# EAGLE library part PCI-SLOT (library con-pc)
PCI SLOT
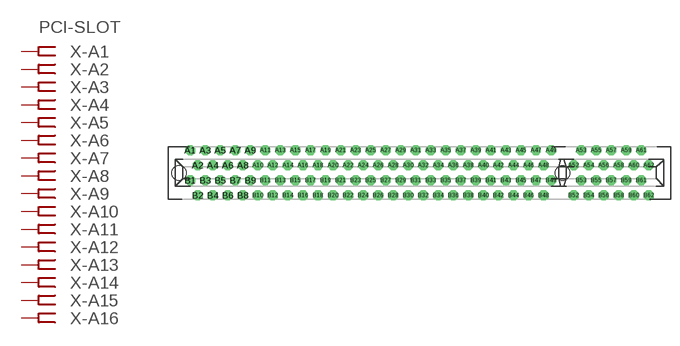
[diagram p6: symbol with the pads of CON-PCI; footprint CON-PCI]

Designator prefix X; gates -A1=FEMRVAL -A2=FEMREC -A3=FEMREC -A4=FEMREC -A5=FEMREC -A6=FEMREC -A7=FEMREC -A8=FEMREC -A9=FEMREC -A10=FEMREC -A11=FEMREC -A12=FEMREC -A13=FEMREC -A14=FEMREC -A15=FEMREC -A16=FEMREC -A17=FEMREC -A18=FEMREC -A19=FEMREC -A20=FEMREC -A21=FEMREC -A22=FEMREC -A23=FEMREC -A24=FEMREC -A25=FEMREC -A26=FEMREC -A27=FEMREC -A28=FEMREC -A29=FEMREC -A30=FEMREC -A31=FEMREC -A32=FEMREC -A33=FEMREC -A34=FEMREC -A35=FEMREC -A36=FEMREC -A37=FEMREC -A38=FEMREC -A39=FEMREC -A40=FEMREC -A41=FEMREC -A42=FEMREC -A43=FEMREC -A44=FEMREC -A45=FEMREC -A46=FEMREC -A47=FEMREC -A48=FEMREC -A49=FEMREC -A52=FEMREC -A53=FEMREC -A54=FEMREC -A55=FEMREC -A56=FEMREC -A57=FEMREC -A58=FEMREC -A59=FEMREC -A60=FEMREC -A61=FEMREC -A62=FEMREC -B1=FEMRVAL -B2=FEMREC -B3=FEMREC -B4=FEMREC -B5=FEMREC -B6=FEMREC -B7=FEMREC -B8=FEMREC -B9=FEMREC -B10=FEMREC -B11=FEMREC -B12=FEMREC -B13=FEMREC -B14=FEMREC -B15=FEMREC -B16=FEMREC -B17=FEMREC -B18=FEMREC -B19=FEMREC -B20=FEMREC -B21=FEMREC -B22=FEMREC -B23=FEMREC -B24=FEMREC -B25=FEMREC -B26=FEMREC -B27=FEMREC -B28=FEMREC -B29=FEMREC -B30=FEMREC -B31=FEMREC -B32=FEMREC -B33=FEMREC -B34=FEMREC -B35=FEMREC -B36=FEMREC -B37=FEMREC -B38=FEMREC -B39=FEMREC -B40=FEMREC -B41=FEMREC -B42=FEMREC -B43=FEMREC -B44=FEMREC -B45=FEMREC -B46=FEMREC -B47=FEMREC -B48=FEMREC -B49=FEMREC -B52=FEMREC -B53=FEMREC -B54=FEMREC -B55=FEMREC -B56=FEMREC -B57=FEMREC -B58=FEMREC -B59=FEMREC -B60=FEMREC -B61=FEMREC -B62=FEMREC

## PCI-SLOT  [CON-PCI]
A1  -A1:P  pas
A2  -A2:P  pas
A3  -A3:P  pas
A4  -A4:P  pas
A5  -A5:P  pas
A6  -A6:P  pas
A7  -A7:P  pas
A8  -A8:P  pas
A9  -A9:P  pas
A10  -A10:P  pas
A11  -A11:P  pas
A12  -A12:P  pas
A13  -A13:P  pas
A14  -A14:P  pas
A15  -A15:P  pas
A16  -A16:P  pas
A17  -A17:P  pas
A18  -A18:P  pas
A19  -A19:P  pas
A20  -A20:P  pas
A21  -A21:P  pas
A22  -A22:P  pas
A23  -A23:P  pas
A24  -A24:P  pas
A25  -A25:P  pas
A26  -A26:P  pas
A27  -A27:P  pas
A28  -A28:P  pas
A29  -A29:P  pas
A30  -A30:P  pas
A31  -A31:P  pas
A32  -A32:P  pas
A33  -A33:P  pas
A34  -A34:P  pas
A35  -A35:P  pas
A36  -A36:P  pas
A37  -A37:P  pas
A38  -A38:P  pas
A39  -A39:P  pas
A40  -A40:P  pas
A41  -A41:P  pas
A42  -A42:P  pas
A43  -A43:P  pas
A44  -A44:P  pas
A45  -A45:P  pas
A46  -A46:P  pas
A47  -A47:P  pas
A48  -A48:P  pas
A49  -A49:P  pas
A52  -A52:P  pas
A53  -A53:P  pas
A54  -A54:P  pas
A55  -A55:P  pas
A56  -A56:P  pas
A57  -A57:P  pas
A58  -A58:P  pas
A59  -A59:P  pas
A60  -A60:P  pas
A61  -A61:P  pas
A62  -A62:P  pas
B1  -B1:P  pas
B2  -B2:P  pas
B3  -B3:P  pas
B4  -B4:P  pas
B5  -B5:P  pas
B6  -B6:P  pas
B7  -B7:P  pas
B8  -B8:P  pas
B9  -B9:P  pas
B10  -B10:P  pas
B11  -B11:P  pas
B12  -B12:P  pas
B13  -B13:P  pas
B14  -B14:P  pas
B15  -B15:P  pas
B16  -B16:P  pas
B17  -B17:P  pas
B18  -B18:P  pas
B19  -B19:P  pas
B20  -B20:P  pas
B21  -B21:P  pas
B22  -B22:P  pas
B23  -B23:P  pas
B24  -B24:P  pas
B25  -B25:P  pas
B26  -B26:P  pas
B27  -B27:P  pas
B28  -B28:P  pas
B29  -B29:P  pas
B30  -B30:P  pas
B31  -B31:P  pas
B32  -B32:P  pas
B33  -B33:P  pas
B34  -B34:P  pas
B35  -B35:P  pas
B36  -B36:P  pas
B37  -B37:P  pas
B38  -B38:P  pas
B39  -B39:P  pas
B40  -B40:P  pas
B41  -B41:P  pas
B42  -B42:P  pas
B43  -B43:P  pas
B44  -B44:P  pas
B45  -B45:P  pas
B46  -B46:P  pas
B47  -B47:P  pas
B48  -B48:P  pas
B49  -B49:P  pas
B52  -B52:P  pas
B53  -B53:P  pas
B54  -B54:P  pas
B55  -B55:P  pas
B56  -B56:P  pas
B57  -B57:P  pas
B58  -B58:P  pas
B59  -B59:P  pas
B60  -B60:P  pas
B61  -B61:P  pas
B62  -B62:P  pas

## Footprint CON-PCI (pad centres in mm)
PCI SLOT
drill 1.016 pad 1.676 octagon: A1 -38.735,3.81; A2 -37.465,1.27; A3 -36.195,3.81; A4 -34.925,1.27; A5 -33.655,3.81; A6 -32.385,1.27; A7 -31.115,3.81; A8 -29.845,1.27; A9 -28.575,3.81; A10 -27.305,1.27; A11 -26.035,3.81; A12 -24.765,1.27; A13 -23.495,3.81; A14 -22.225,1.27; A15 -20.955,3.81; A16 -19.685,1.27; A17 -18.415,3.81; A18 -17.145,1.27; A19 -15.875,3.81; A20 -14.605,1.27; A21 -13.335,3.81; A22 -12.065,1.27; A23 -10.795,3.81; A24 -9.525,1.27; A25 -8.255,3.81; A26 -6.985,1.27; A27 -5.715,3.81; A28 -4.445,1.27; A29 -3.175,3.81; A30 -1.905,1.27; A31 -0.635,3.81; A32 0.635,1.27; A33 1.905,3.81; A34 3.175,1.27; A35 4.445,3.81; A36 5.715,1.27; A37 6.985,3.81; A38 8.255,1.27; A39 9.525,3.81; A40 10.795,1.27; A41 12.065,3.81; A42 13.335,1.27; A43 14.605,3.81; A44 15.875,1.27; A45 17.145,3.81; A46 18.415,1.27; A47 19.685,3.81; A48 20.955,1.27; A49 22.225,3.81; A52 26.035,1.27; A53 27.305,3.81; A54 28.575,1.27; A55 29.845,3.81; A56 31.115,1.27; A57 32.385,3.81; A58 33.655,1.27; A59 34.925,3.81; A60 36.195,1.27; A61 37.465,3.81; A62 38.735,1.27; B1 -38.735,-1.27; B2 -37.465,-3.81; B3 -36.195,-1.27; B4 -34.925,-3.81; B5 -33.655,-1.27; B6 -32.385,-3.81; B7 -31.115,-1.27; B8 -29.845,-3.81; B9 -28.575,-1.27; B10 -27.305,-3.81; B11 -26.035,-1.27; B12 -24.765,-3.81; B13 -23.495,-1.27; B14 -22.225,-3.81; B15 -20.955,-1.27; B16 -19.685,-3.81; B17 -18.415,-1.27; B18 -17.145,-3.81; B19 -15.875,-1.27; B20 -14.605,-3.81; B21 -13.335,-1.27; B22 -12.065,-3.81; B23 -10.795,-1.27; B24 -9.525,-3.81; B25 -8.255,-1.27; B26 -6.985,-3.81; B27 -5.715,-1.27; B28 -4.445,-3.81; B29 -3.175,-1.27; B30 -1.905,-3.81; B31 -0.635,-1.27; B32 0.635,-3.81; B33 1.905,-1.27; B34 3.175,-3.81; B35 4.445,-1.27; B36 5.715,-3.81; B37 6.985,-1.27; B38 8.255,-3.81; B39 9.525,-1.27; B40 10.795,-3.81; B41 12.065,-1.27; B42 13.335,-3.81; B43 14.605,-1.27; B44 15.875,-3.81; B45 17.145,-1.27; B46 18.415,-3.81; B47 19.685,-1.27; B48 20.955,-3.81; B49 22.225,-1.27; B52 26.035,-3.81; B53 27.305,-1.27; B54 28.575,-3.81; B55 29.845,-1.27; B56 31.115,-3.81; B57 32.385,-1.27; B58 33.655,-3.81; B59 34.925,-1.27; B60 36.195,-3.81; B61 37.465,-1.27; B62 38.735,-3.81
hole 2.438 at 24.13,0
hole 2.438 at -40.64,0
